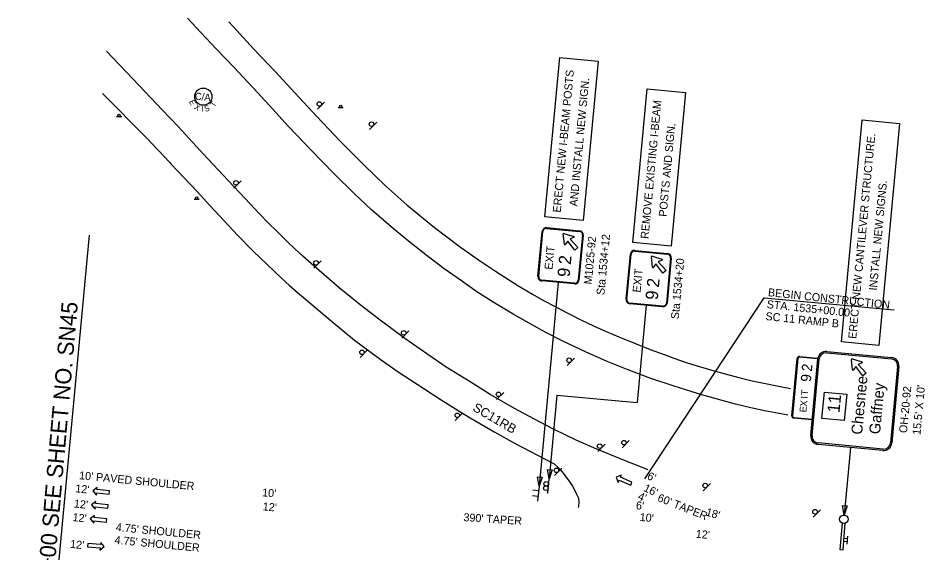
# Model space of a CAD drawing. Extents: x 1800374 to 1802004, y 1187708 to 1188617.
# Drawn here: x 1800374 to 1801167, y 1188150 to 1188617 of the extents above; entities that cross this region are included whole.
import ezdxf

# ---------------------------------------------------------------- set-up
doc = ezdxf.new("R2010")
doc.units = 0
for name, color, linetype in [('RD_EX_Road', 7, 'Continuous'), ('RD_PD_Final_LnLine', 7, 'Continuous'), ('RD_PD_Final_TX', 7, 'Continuous'), ('RD_SHT_MatchLine', 7, 'Continuous'), ('RD_SHT_TX', 7, 'Continuous'), ('RD_Sketch8', 7, 'Continuous'), ('RD_TX_RoadID', 7, 'Continuous'), ('SN_P_Signs', 7, 'Continuous')]:
    doc.layers.add(name, color=color, linetype=linetype)

# ---------------------------------------------------------------- blocks, each defined once
blk = doc.blocks.new('SARRW2')
at = {"layer": 'RD_PD_Final_LnLine'}
blk.add_lwpolyline([(-12, 1.2), (-12, -1.2), (-2.83, -1.2), (-2.83, -2.83), (0, 0), (-2.83, 2.83), (-2.83, 1.2)], close=True, dxfattribs=at)

msp = doc.modelspace()

# ---------------------------------------------------------------- linework, layer by layer
at = {"layer": 'RD_EX_Road'}
for points in [[(1801047.24, 1188270.04), (1801042.86, 1188270.78), (1801030.04, 1188273.2), (1801028.21, 1188273.56), (1801014.76, 1188276.54), (1801001.37, 1188279.74), (1800989.73, 1188282.72), (1800972, 1188287.72), (1800963.44, 1188290.3), (1800946.86, 1188295.57), (1800927.4, 1188302.08), (1800906.83, 1188309.88), (1800889.3, 1188316.96), (1800870.2, 1188325.5), (1800851.13, 1188334.4), (1800835.55, 1188342.34), (1800823.1, 1188349.19), (1800807.16, 1188358.3), (1800789.48, 1188368.89), (1800774.52, 1188378.38), (1800761.75, 1188387.4), (1800746.67, 1188398.14), (1800730.62, 1188410.41), (1800713.95, 1188423.45), (1800700.21, 1188434.71), (1800683.13, 1188449.58), (1800667.86, 1188463.79), (1800650.54, 1188481.01), (1800639.89, 1188491.77), (1800629.4, 1188502.7), (1800624.25, 1188508.19), (1800610.33, 1188522.9), (1800596.95, 1188537.76), (1800583.37, 1188552.17), (1800562.97, 1188574.03), (1800547.52, 1188590.14), (1800533.9, 1188604.86), (1800522.14, 1188617.32)], [(1801047.24, 1188270.04), (1801042.86, 1188270.78), (1801030.04, 1188273.2), (1801028.21, 1188273.56), (1801014.76, 1188276.54), (1801001.37, 1188279.74), (1800989.73, 1188282.72), (1800972, 1188287.72), (1800963.44, 1188290.3), (1800946.86, 1188295.57), (1800927.4, 1188302.08), (1800906.83, 1188309.88), (1800889.3, 1188316.96), (1800870.2, 1188325.5), (1800851.13, 1188334.4), (1800835.55, 1188342.34), (1800823.1, 1188349.19), (1800807.16, 1188358.3), (1800789.48, 1188368.89), (1800774.52, 1188378.38), (1800761.75, 1188387.4), (1800746.67, 1188398.14), (1800730.62, 1188410.41), (1800713.95, 1188423.45), (1800700.21, 1188434.71), (1800683.13, 1188449.58), (1800667.86, 1188463.79), (1800650.54, 1188481.01), (1800639.89, 1188491.77), (1800629.4, 1188502.7), (1800624.25, 1188508.19), (1800610.33, 1188522.9), (1800596.95, 1188537.76), (1800583.37, 1188552.17), (1800562.97, 1188574.03), (1800547.52, 1188590.14), (1800533.9, 1188604.86), (1800522.14, 1188617.32)], [(1800558.3, 1188613.94), (1800562.07, 1188609.91), (1800580.03, 1188590.56), (1800598.59, 1188570.84), (1800616.23, 1188552.01), (1800635.22, 1188531.41), (1800655.79, 1188509.78), (1800676.77, 1188488.58), (1800695.81, 1188470.3), (1800714.1, 1188454), (1800738.23, 1188434.14), (1800759.73, 1188417.99), (1800776.85, 1188405.85), (1800791.6, 1188395.97), (1800811.17, 1188383.58), (1800814.16, 1188381.74), (1800823.86, 1188375.94), (1800833.69, 1188370.34), (1800843.63, 1188364.95), (1800853.68, 1188359.77), (1800855.44, 1188358.86), (1800866.27, 1188353.46), (1800877.21, 1188348.27), (1800888.24, 1188343.29), (1800899.37, 1188338.53), (1800902.33, 1188337.28), (1800914.49, 1188332.3), (1800926.73, 1188327.54), (1800939.06, 1188323.01), (1800947.67, 1188319.9), (1800959.25, 1188315.94), (1800970.91, 1188312.2), (1800980.86, 1188309.39), (1800992.53, 1188306.08), (1801004.26, 1188303), (1801016.06, 1188300.14), (1801026.09, 1188297.9), (1801039.07, 1188295.3), (1801049.42, 1188293.41)], [(1800925.2, 1188222.15), (1800901.47, 1188231.48), (1800880.32, 1188240.32), (1800862.13, 1188248.26), (1800842.44, 1188257.85), (1800825.12, 1188266.9), (1800808.32, 1188275.96), (1800786.96, 1188288.17), (1800769.32, 1188299.11), (1800748.56, 1188312.1), (1800732.5, 1188323.01), (1800712.24, 1188337.1), (1800690.81, 1188353.16), (1800673.27, 1188366.61), (1800654.97, 1188381.4), (1800637.49, 1188396.65), (1800630.26, 1188402.74), (1800623.18, 1188409.01), (1800616.26, 1188415.45), (1800609.5, 1188422.07), (1800608.67, 1188422.91), (1800600.61, 1188430.54), (1800592.71, 1188438.35), (1800584.99, 1188446.32), (1800577.43, 1188454.45), (1800577.05, 1188454.86), (1800553.58, 1188479.89), (1800536.22, 1188498.46), (1800513.7, 1188522.91), (1800500.51, 1188536.68), (1800480.01, 1188558.5), (1800451.46, 1188588.37)], [(1800448, 1188551.43), (1800486.28, 1188512.68), (1800496.6, 1188501.9), (1800506.73, 1188490.97), (1800507.61, 1188490.01), (1800530.67, 1188465.55), (1800541.88, 1188453.53), (1800554.06, 1188440.28), (1800566.41, 1188427.2), (1800578.93, 1188414.27), (1800579.76, 1188413.43), (1800604.33, 1188389.92), (1800611.37, 1188383.48), (1800618.58, 1188377.2), (1800625.45, 1188371.5), (1800647.94, 1188352.46), (1800668.32, 1188335.5), (1800690.76, 1188319.04), (1800706.46, 1188308.06), (1800723.04, 1188297.1), (1800744.08, 1188283.36), (1800758.86, 1188274.09), (1800769.36, 1188267.77), (1800791.04, 1188255.29), (1800808.68, 1188245.26), (1800828.43, 1188235.07), (1800842.79, 1188227.4), (1800845.66, 1188224.85), (1800848.36, 1188222.12), (1800850.89, 1188219.23), (1800853.23, 1188216.19), (1800854.36, 1188214.59), (1800856.7, 1188211.38), (1800858.85, 1188208.03), (1800860.8, 1188204.57), (1800862.54, 1188200.99), (1800864.06, 1188197.32), (1800864.07, 1188197.29), (1800864.49, 1188193.94), (1800864.18, 1188190.48), (1800863.87, 1188189.32), (1800863.77, 1188189.12)]]:
    msp.add_lwpolyline(points, dxfattribs=at)
at = {"layer": 'RD_PD_Final_TX'}
for p, q in [((1800922.11, 1188214.24), (1801026.59, 1188372.66)), ((1801026.59, 1188372.66), (1801140.33, 1188362.02))]:
    msp.add_line(p, q, dxfattribs=at)
at = {"layer": 'RD_SHT_MatchLine'}
msp.add_line((1800436.4, 1188427.36), (1800386.22, 1187890.97), dxfattribs=at)
at = {"layer": 'RD_Sketch8'}
msp.add_circle((1800536.1, 1188548.65), 7.5, dxfattribs=at)
at = {"layer": 'SN_P_Signs'}
for p, q in [((1800834.82, 1188443.49), (1800847.87, 1188582.9)), ((1800847.87, 1188582.9), (1800881.34, 1188579.77)), ((1800881.34, 1188579.77), (1800868.29, 1188440.35)), ((1800911.64, 1188420.98), (1800924.22, 1188555.41)), ((1800924.22, 1188555.41), (1800957.69, 1188552.28)), ((1800957.69, 1188552.28), (1800945.11, 1188417.84)), ((1800635.8, 1188537.57), (1800642.16, 1188543.93)), ((1800653.99, 1188539.09), (1800658.49, 1188539.09)), ((1800460.22, 1188531.34), (1800464.72, 1188531.34)), ((1800681.41, 1188519.89), (1800687.78, 1188526.26)), ((1801094.17, 1188334.13), (1801112.33, 1188528.28)), ((1801112.33, 1188528.28), (1801145, 1188525.22)), ((1801145, 1188525.22), (1801126.83, 1188331.07)), ((1800562.92, 1188468.62), (1800569.29, 1188474.98)), ((1800528.1, 1188458.86), (1800532.6, 1188458.86)), ((1800868.29, 1188440.35), (1800834.82, 1188443.49)), ((1800828.75, 1188391.37), (1800832.44, 1188430.8)), ((1800829.35, 1188391.32), (1800833.04, 1188430.74)), ((1800836.3, 1188433.45), (1800864.98, 1188430.77)), ((1800836.36, 1188434.05), (1800865.03, 1188431.37)), ((1800867.69, 1188427.5), (1800864, 1188388.08)), ((1800868.28, 1188427.45), (1800864.6, 1188388.02)), ((1800945.11, 1188417.84), (1800911.64, 1188420.98)), ((1800905.81, 1188371.4), (1800909.5, 1188410.83)), ((1800906.4, 1188371.34), (1800910.09, 1188410.77)), ((1800913.36, 1188413.48), (1800942.03, 1188410.8)), ((1800913.41, 1188414.07), (1800942.09, 1188411.39)), ((1800632.83, 1188398.57), (1800639.19, 1188404.94)), ((1800944.74, 1188407.53), (1800941.05, 1188368.1)), ((1800945.34, 1188407.47), (1800941.65, 1188368.04)), ((1800860.68, 1188384.77), (1800832, 1188387.45)), ((1800860.73, 1188385.37), (1800832.06, 1188388.05)), ((1800846.34, 1188386.11), (1800829.66, 1188207.81)), ((1800937.73, 1188364.8), (1800909.06, 1188367.48)), ((1800937.79, 1188365.39), (1800909.11, 1188368.08)), ((1800923.39, 1188366.14), (1800915.44, 1188281.09)), ((1800709.55, 1188337.43), (1800715.91, 1188343.79)), ((1801126.83, 1188331.07), (1801094.17, 1188334.13)), ((1800673.13, 1188320.39), (1800679.49, 1188326.76)), ((1801081.18, 1188324.49), (1801137.81, 1188319.19)), ((1800854.2, 1188313.43), (1800860.56, 1188319.79)), ((1800792.42, 1188283.62), (1800798.79, 1188289.99)), ((1800845.28, 1188287.65), (1800838.41, 1188214.19)), ((1800845.28, 1188287.65), (1800915.44, 1188281.09)), ((1801079.16, 1188290.1), (1801098.77, 1188288.26)), ((1801098.77, 1188288.26), (1801096.62, 1188265.29)), ((1800756.42, 1188265.28), (1800762.79, 1188271.64)), ((1801096.62, 1188265.29), (1801077.02, 1188267.13)), ((1800880.98, 1188238.31), (1800887.34, 1188244.67)), ((1800902.21, 1188241.36), (1800908.58, 1188247.72)), ((1801130.44, 1188240.41), (1801073.81, 1188245.71)), ((1801102.01, 1188241.87), (1801096.47, 1188182.6)), ((1800843.2, 1188217.18), (1800849.57, 1188223.54)), ((1800837.57, 1188205.22), (1800838.41, 1188214.19)), ((1800829.66, 1188207.81), (1800828.44, 1188194.82)), ((1800837.22, 1188201.49), (1800838.06, 1188210.45)), ((1800973.19, 1188203.85), (1800979.55, 1188210.21)), ((1800828.83, 1188198.92), (1800823.86, 1188199.38)), ((1800829.29, 1188203.91), (1800824.33, 1188204.38)), ((1801069.29, 1188180.93), (1801075.65, 1188187.3)), ((1801096.18, 1188159.67), (1801098.95, 1188159.44)), ((1801096.4, 1188162.33), (1801099.15, 1188162.11)), ((1801099.31, 1188164.2), (1801098.75, 1188157.27))]:
    msp.add_line(p, q, dxfattribs=at)
for points in [[(1800851.82, 1188419.55), (1800850.9, 1188428.53)], [(1800851.48, 1188429.01), (1800860.13, 1188426.44)], [(1800854.81, 1188422.29), (1800852.63, 1188419.33)], [(1800863.65, 1188416.56), (1800860.88, 1188414.27), (1800854.81, 1188422.29)], [(1800860.2, 1188425.61), (1800856.89, 1188424.01)], [(1800856.89, 1188424.01), (1800863.65, 1188416.56)], [(1800928.88, 1188399.58), (1800927.96, 1188408.56)], [(1800928.53, 1188409.04), (1800937.19, 1188406.47)], [(1800937.26, 1188405.63), (1800933.94, 1188404.04)], [(1800933.94, 1188404.04), (1800940.7, 1188396.59)], [(1800931.87, 1188402.32), (1800929.69, 1188399.36)], [(1800940.7, 1188396.59), (1800937.93, 1188394.29), (1800931.87, 1188402.32)], [(1801081.3, 1188325.68), (1801137.92, 1188320.39)], [(1801050.73, 1188269.49), (1801055.42, 1188319.67)], [(1801056.02, 1188319.61), (1801051.33, 1188269.43)], [(1801073.46, 1188319.19), (1801057.33, 1188320.69)], [(1801057.38, 1188321.29), (1801073.51, 1188319.78), (1801073.46, 1188319.19)], [(1801067.2, 1188252.35), (1801073.46, 1188319.19)], [(1801068.4, 1188252.24), (1801074.65, 1188319.07)], [(1801103.77, 1188309.77), (1801102.85, 1188318.75)], [(1801103.43, 1188319.22), (1801112.08, 1188316.66)], [(1801112.15, 1188315.82), (1801108.84, 1188314.23)], [(1801106.76, 1188312.5), (1801104.58, 1188309.54)], [(1801115.6, 1188306.78), (1801112.83, 1188304.48), (1801106.76, 1188312.5)], [(1801108.84, 1188314.23), (1801115.6, 1188306.78)], [(1801143.22, 1188312.66), (1801136.97, 1188245.83)], [(1801144.42, 1188312.55), (1801138.17, 1188245.71)], [(1801077.02, 1188267.13), (1801079.16, 1188290.1)], [(1801052.41, 1188268.12), (1801068.54, 1188266.62), (1801068.48, 1188266.02), (1801052.35, 1188267.53)], [(1801130.33, 1188239.22), (1801073.7, 1188244.51)], [(1801094.67, 1188175.49), (1801092.78, 1188152.44), (1801095.57, 1188152.21), (1801097.47, 1188175.45)]]:
    msp.add_lwpolyline(points, dxfattribs=at)
for points in [[(1800841.22, 1188222.16), (1800838.41, 1188214.19), (1800837.13, 1188222.54)], [(1800832.46, 1188215.78), (1800829.66, 1188207.81), (1800828.38, 1188216.16)], [(1801099.14, 1188190.61), (1801096.43, 1188182.6), (1801095.06, 1188190.95)]]:
    msp.add_lwpolyline(points, close=True, dxfattribs=at)
for centre, radius in [((1800637.56, 1188542.2), 2), ((1800656.25, 1188540.1), 1), ((1800462.48, 1188532.35), 1), ((1800683.17, 1188524.52), 2), ((1800564.68, 1188473.24), 2), ((1800530.36, 1188459.88), 1), ((1800634.59, 1188403.2), 2), ((1800711.31, 1188342.05), 2), ((1800674.89, 1188325.02), 2), ((1800855.96, 1188318.05), 2), ((1800794.18, 1188288.25), 2), ((1800758.18, 1188269.91), 2), ((1800882.74, 1188242.94), 2), ((1800903.98, 1188245.98), 2), ((1800844.96, 1188221.8), 2), ((1800835.63, 1188206.17), 2), ((1800835.98, 1188209.91), 2), ((1800974.95, 1188208.47), 2), ((1801071.05, 1188185.56), 2), ((1801096.12, 1188178.91), 3.71)]:
    msp.add_circle(centre, radius, dxfattribs=at)
for centre, radius, start, end in [((1800836.02, 1188430.47), 3.6, 84.65568, 174.65568), ((1800836.02, 1188430.47), 3, 84.65568, 174.65568), ((1800851.35, 1188428.58), 0.45, 73.47778, 185.83358), ((1800864.7, 1188427.78), 3, 354.65568, 84.65568), ((1800864.7, 1188427.78), 3.6, 354.65568, 84.65568), ((1800852.27, 1188419.6), 0.45, 185.83358, 323.61778), ((1800860.01, 1188426.01), 0.45, 295.69358, 73.47778), ((1800913.08, 1188410.49), 3.6, 84.65568, 174.65568), ((1800913.08, 1188410.49), 3, 84.65568, 174.65568), ((1800941.75, 1188407.81), 3, 354.65568, 84.65568), ((1800941.75, 1188407.81), 3.6, 354.65568, 84.65568), ((1800928.41, 1188408.6), 0.45, 73.47778, 185.83358), ((1800937.06, 1188406.04), 0.45, 295.69358, 73.47778), ((1800929.32, 1188399.62), 0.45, 185.83358, 323.61778), ((1800832.34, 1188391.04), 3.6, 174.65568, 264.65568), ((1800832.34, 1188391.04), 3, 174.65568, 264.65568), ((1800861.01, 1188388.35), 3.6, 264.65568, 354.65568), ((1800861.01, 1188388.35), 3, 264.65568, 354.65568), ((1800909.39, 1188371.06), 3.6, 174.65568, 264.65568), ((1800909.39, 1188371.06), 3, 174.65568, 264.65568), ((1800938.07, 1188368.38), 3.6, 264.65568, 354.65568), ((1800938.07, 1188368.38), 3, 264.65568, 354.65568), ((1801080.62, 1188318.52), 7.2, 84.65568, 174.65568), ((1801080.62, 1188318.52), 6, 84.65568, 174.65568), ((1801057.21, 1188319.5), 1.8, 84.65568, 174.65568), ((1801057.21, 1188319.5), 1.2, 84.65568, 174.65568), ((1801103.3, 1188318.79), 0.45, 73.47778, 185.83358), ((1801111.95, 1188316.23), 0.45, 295.69358, 73.47778), ((1801137.25, 1188313.22), 6, 354.65568, 84.65568), ((1801137.25, 1188313.22), 7.2, 354.65568, 84.65568), ((1801104.22, 1188309.81), 0.45, 185.83358, 323.61778), ((1801052.52, 1188269.32), 1.8, 174.65568, 264.65568), ((1801052.52, 1188269.32), 1.2, 174.65568, 264.65568), ((1801074.37, 1188251.68), 7.2, 174.65568, 264.65568), ((1801074.37, 1188251.68), 6, 174.65568, 264.65568), ((1801131, 1188246.39), 7.2, 264.65568, 354.65568), ((1801131, 1188246.39), 6, 264.65568, 354.65568)]:
    msp.add_arc(centre, radius, start, end, dxfattribs=at)

# ---------------------------------------------------------------- block references
at = {"layer": 'RD_PD_Final_LnLine'}
for p, xscale, yscale, rotation in [((1800897.1, 1188215.72), 1.1999999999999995, 1.200000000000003, 157.0915362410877), ((1800439.51, 1188203.78), 1.1999999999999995, 1.200000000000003, 174.65567699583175), ((1800438.36, 1188191.55), 1.1999999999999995, 1.200000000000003, 174.65567699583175), ((1800437.22, 1188179.32), 1.1999999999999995, 1.200000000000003, 174.65567699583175), ((1800449.41, 1188155.09), 1.1999999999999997, 1.2000000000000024, -5.34432300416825)]:
    msp.add_blockref('SARRW2', p, dxfattribs=dict(at, xscale=xscale, yscale=yscale, rotation=rotation))

# ---------------------------------------------------------------- texts
at = {"layer": 'RD_PD_Final_TX'}
for s, rotation, p in [('BEGIN CONSTRUCTION', 354.02886, (1801029.61, 1188374.17)), ('STA. 1535+00.00', 354.02886, (1801028.52, 1188363.73)), ('SC 11 RAMP B', 354.02886, (1801027.43, 1188353.28)), ("10' PAVED SHOULDER", 354.54177, (1800427.26, 1188214.04)), ("6'", 333.95194, (1800923.52, 1188214.52)), ("12'", 354.02886, (1800423.88, 1188202.65)), ("10'", 354.65568, (1800587.29, 1188199.12)), ("16'", 334.62923, (1800920.44, 1188204.01)), ("4'", 338.16831, (1800915.43, 1188196.5)), ("60' TAPER", 338.31003, (1800932.63, 1188195.12)), ("12'", 353.95121, (1800422.64, 1188189.36)), ("12'", 354.65568, (1800587.83, 1188186.84)), ("6'", 354.76418, (1800914.18, 1188187.82)), ("12'", 354.02886, (1800421.52, 1188177.45)), ("390' TAPER", 356.33679, (1800763.41, 1188177.34)), ("10'", 354.76418, (1800917.44, 1188177.57)), ("18'", 343.41924, (1800974.95, 1188182.45)), ("4.75' SHOULDER", 354.65568, (1800459.34, 1188168.67)), ("12'", 354.76418, (1800966.5, 1188162.85)), ("12'", 353.95121, (1800419.34, 1188154.04)), ("4.75' SHOULDER", 354.65568, (1800458.3, 1188157.52))]:
    msp.add_text(s, height=7, rotation=rotation, dxfattribs=at).set_placement(p)
at = {"layer": 'RD_SHT_TX'}
msp.add_text('MATCHLINE STA. 1530+00 SEE SHEET NO. SN45', height=14.1726, rotation=84.99841, dxfattribs=at).set_placement((1800388.14, 1187930.52))
at = {"layer": 'RD_Sketch8'}
for s, height, rotation, p in [('E', 5, 297.86692, (1800523.42, 1188544.29)), ('C/A', 6.25, 354.65568, (1800528.41, 1188546.08)), ('X', 5, 330.29629, (1800527.65, 1188538.22)), ('I', 5, 354.45629, (1800534.21, 1188535.52)), ('S', 5, 16.44812, (1800537.86, 1188535.36)), ('T', 5, 52.84082, (1800545.43, 1188539.03))]:
    msp.add_text(s, height=height, rotation=rotation, dxfattribs=at).set_placement(p)
at = {"layer": 'RD_TX_RoadID'}
msp.add_text('SC11RB', height=8, rotation=329.73882, dxfattribs=at).set_placement((1800770.98, 1188274.43))
at = {"layer": 'SN_P_Signs'}
for s, height, rotation, p in [('ERECT NEW I-BEAM POSTS', 6.9998, 84.65576, (1800848.57, 1188447)), ('AND INSTALL NEW SIGN.', 6.9998, 84.65576, (1800863.14, 1188452.36)), ('REMOVE EXISTING I-BEAM', 6.9998, 84.65576, (1800925.35, 1188424)), ('POSTS AND SIGN.', 6.9998, 84.65576, (1800941.21, 1188443.32)), ('ERECT NEW CANTILEVER STRUCTURE.', 7, 84.65576, (1801107, 1188336.58)), ('INSTALL NEW SIGNS.', 7, 84.65576, (1801125.02, 1188378.83)), ('Sta 1534+12', 7, 84.65576, (1800886.79, 1188374.88)), ('M1025-92', 7, 84.65576, (1800875.71, 1188384.17)), ('EXIT', 7, 84.65568, (1800841.33, 1188397.03)), ('2', 10.8, 84.65568, (1800857.41, 1188401.34)), ('Sta 1534+20', 7, 84.65576, (1800951.79, 1188353.77)), ('9', 10.8, 84.65568, (1800856.39, 1188390.47)), ('EXIT', 7, 84.65568, (1800918.39, 1188377.05)), ('2', 10.8, 84.65568, (1800934.46, 1188381.37)), ('9', 10.8, 84.65568, (1800933.44, 1188370.49)), ('2', 9, 84.65568, (1801068.18, 1188307.89)), ('9', 9, 84.65568, (1801067.33, 1188298.82)), ('Chesnee', 9.6, 84.65568, (1801112.13, 1188252.68)), ('T', 6, 84.65568, (1801064.73, 1188287.14)), ('Gaffney', 9.6, 84.65568, (1801127.8, 1188253.05)), ('OH-20-92', 7, 84.65576, (1801151.38, 1188254.11)), ("15.5' X 10'", 7, 84.65576, (1801163.18, 1188252.56)), ('I', 6, 84.65568, (1801064.46, 1188284.17)), ('11', 10.8, 84.65568, (1801092.37, 1188271.74)), ('E', 6, 84.65568, (1801063.34, 1188272.26)), ('X', 6, 84.65568, (1801063.82, 1188277.39))]:
    msp.add_text(s, height=height, rotation=rotation, dxfattribs=at).set_placement(p)

doc.saveas('drawing.dxf')
